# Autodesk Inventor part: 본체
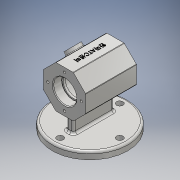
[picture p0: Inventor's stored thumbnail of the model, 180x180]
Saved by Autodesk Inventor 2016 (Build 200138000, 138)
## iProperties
Created: 2021-02
Part Number: 본체
Material: 알루미늄 6061
Document SubType Name: Modeling
Designer: Windows7
Density: 2.7 g/cm^3
Appearance: 알루미늄 - 평지
Mass: 555.802 g
Surface Area: 511.823 cm^2
Volume: 205.853 cm^3
Author: Windows7
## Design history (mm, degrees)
sketch "스케치1"
  geometry: C1 r 52 at (0, 0); 1 further point
  constraints: 1 centre point, 1 coincident
  dimensions: "d0" = 104 diameter of C1
extrude "돌출1" new body sketch "스케치1" distance "d1" = 10; taper "d2" = 0 deg
sketch "스케치2"
  geometry: L1 (-35, 62)-(35, 62); L2 (-35, 62)-(-35, 91); L3 (-35, 91)-(35, 91); L4 (35, 91)-(35, 62); L5 (-35, 78)-(-23, 78); L6 (-23, 78)-(-23, 76); L7 (-23, 76)-(-20, 76); L8 (-20, 76)-(-20, 84); L9 (-20, 84)-(20, 84); L10 (23, 78)-(35, 78); L11 (20, 84)-(20, 76); L12 (20, 76)-(23, 76); L13 (23, 76)-(23, 78); 2 further points
  constraints: 26 end point, 9 perpendicular, 4 collinear, 2 horizontal, 2 point on line, 2 vertical, 1 midpoint, 1 vertical alignment
  dimensions: "d3" = 70 distance of L1.start L1.end; "d4" = 62 distance from line of L1 point (0, 0); "d5" = 91 distance from line of point (0, 0) L3; "d6" = 32 diameter of L5 L1; "d7" = 28 diameter of L7 L1; "d8" = 44 diameter of L9 L1; "d9" = 40 distance of L8.end L9.end; "d10" = 12 distance of L5.start L5.end
revolve "회전1" sketch "스케치2" stored, may be unused: angle "d11" = 90 deg
sketch "스케치3" dims "d12" = 46
  geometry: L1 (0, 0)-(0, 23); C1 r 29 at (0, 0) reference; 2 further points
  constraints: 2 coincident, 2 end point, 1 vertical, 1 vertical alignment, 2 other
hole "구멍1" sketch "스케치3" at (0, 23) diameter "d13" = 3.459; stored, may be unused: countersink angle "d17" = 90 deg, drill point angle "d19" = 118 deg; dims "d14" = 8, "d15" = 4, "d16" = 2, "d18" = 10
sketch "스케치4"
  geometry: L1 (12.012, 29)-(29, 12.012); L2 (29, 12.012)-(29, -12.012); L3 (29, -12.012)-(12.012, -29); L4 (12.012, -29)-(-12.012, -29); L5 (-12.012, -29)-(-29, -12.012); L6 (-29, -12.012)-(-29, 12.012); L7 (-29, 12.012)-(-12.012, 29); L8 (-12.012, 29)-(12.012, 29); 5 further points
  constraints: 16 end point, 2 midpoint, 1 coincident, 1 horizontal alignment, 1 vertical alignment, 18 other
extrude "돌출2" join sketch "스케치4" stored distance "d23" = 0; taper "d24" = 0 deg
sketch "스케치5"
  geometry: L1 (5, 28)-(-5, 28); L2 (-5, 28)-(-5, -28); L3 (-5, -28)-(5, -28); L4 (5, -28)-(5, 28); L5 (5, 28)-(-5, -28); L6 (-5, 28)-(5, -28); 1 further point
  constraints: 12 end point, 2 midpoint, 2 parallel, 1 horizontal, 1 perpendicular
  dimensions: "d25" = 10 distance of L2.end L3.end; "d26" = 56 distance of L1.end L2.end
extrude "돌출3" join sketch "스케치5" stored distance "d27" = 10; taper "d28" = 0 deg
sketch "스케치7" dims "d23" = 0
  geometry: L1 (15.014, 55.739)-(15.014, 14.261); L2 (15.014, 14.261)-(9.01, 14.261); L3 (9.01, 14.261)-(9.01, 55.739); L4 (9.01, 55.739)-(15.014, 55.739); L5 (12.012, 14.261)-(12.012, 55.739); L6 (9.01, 35)-(15.014, 35); L7 (-16.988, 0)-(-16.988, 70) reference; 1 further point
  constraints: 4 end point, 2 other
  dimensions: "d42" = 29 distance between parallel lines of L5 L7; "d43" = 35 distance from line of L7.start L6
feature "엠보싱1" sketch "스케치7" dims "d44" = 0.5, "d45" = 0
sketch "스케치8" dims "d46" = 82
  geometry: L1 (0, 0)-(-41, 0); 2 further points
  constraints: 2 coincident, 2 end point, 1 horizontal, 1 horizontal alignment, 2 other
hole "구멍3" sketch "스케치8" at (-41, 0) diameter "d47" = 9; stored, may be unused: countersink angle "d51" = 90 deg, drill point angle "d53" = 118 deg; dims "d48" = 24, "d49" = 4, "d50" = 2, "d52" = 10
fillet "모깎기1" dims "d57" = 0.3, "d58" = 3, "d62" = 1
fillet "모깎기2" dims "d63" = 3
node "작업 평면2"
chamfer "모따기1" distance "d59" = 1; stored, may be unused: second distance "d60" = 2, angle "d61" = 45 deg
sketch "스케치9"
  geometry: L1 (40.598, 0)-(40.598, 70) reference; C1 r 10 at (11.598, 35); 1 further point
  constraints: 1 centre point
  dimensions: "d65" = 20 diameter of C1; "d66" = 29 distance from line of L1 C1.centre; "d67" = 35 vertical distance of L1.end C1.centre
extrude "돌출5" join sketch "스케치9" stored distance "d68" = 10; taper "d69" = 0 deg
fillet "모깎기3" dims "d70" = 1
hole "구멍4" diameter "d73" = 10.917; stored, may be unused: countersink angle "d77" = 90 deg, drill point angle "d79" = 118 deg; dims "d71" = 10, "d72" = 10, "d74" = 24, "d75" = 16, "d76" = 2, "d78" = 29.1
chamfer "모따기2" distance "d80" = 1; stored, may be unused: second distance "d81" = 2, angle "d82" = 45 deg
node "솔리드1"
pattern_circular "원형 패턴1" dims angle "d21" = 360 deg
mirror "대칭1"
pattern_circular "원형 패턴2" dims angle "d55" = 360 deg
other parameters: "d64" = 5
